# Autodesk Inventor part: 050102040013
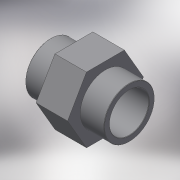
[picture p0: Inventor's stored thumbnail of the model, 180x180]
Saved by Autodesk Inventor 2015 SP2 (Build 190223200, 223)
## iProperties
Created: 2017-10
Part Number: 050102040013
Material: Generic
Description: PLASSON SOCKET ADAPTOR THR-CEM 40-1.1/4"
Document SubType Name: Modeling
Designer: KIM
Density: 1 g/cm^3
Appearance: Default
Author: KIM
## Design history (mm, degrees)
derived "050102.ipt"
feature "Solid1::050102.ipt"
tag "TaggingFeature1"
body "Solid1"
other parameters: "d0" = 52, "d2" = 51, "d3" = 38.952, "d4" = 36, "d5" = 26, "d6" = 22, "d7" = 48, "d8" = 46, "d10" = 15.4, "d13" = 0, "d14" = 0.4, "d15" = 16, "G_" = 38.952, "C_" = 51, "B_" = 16, "l_" = 26, "lt_" = 22, "H_" = 52
